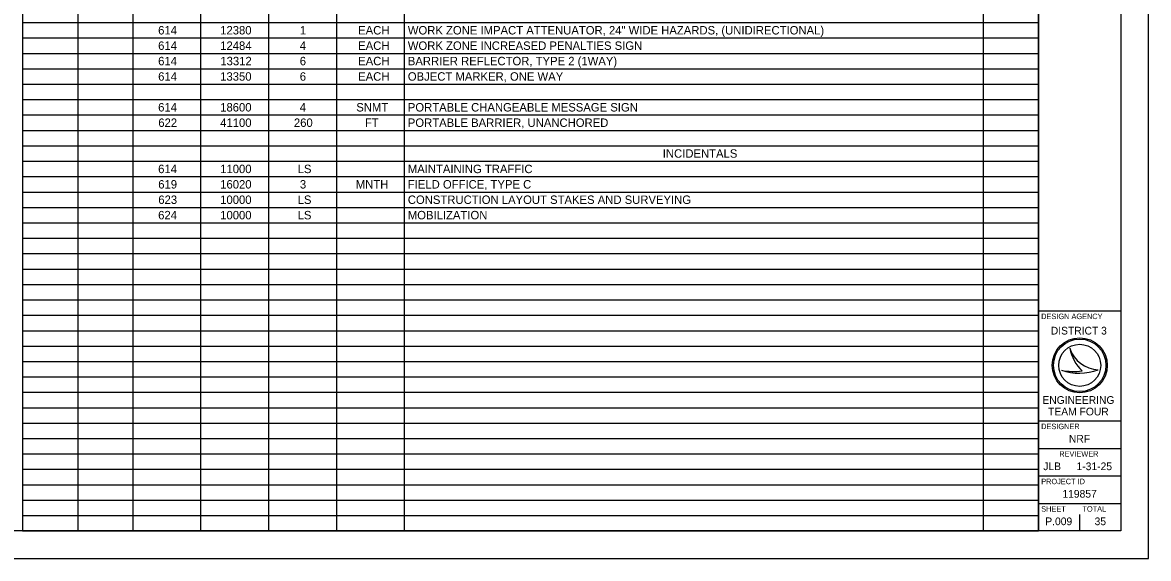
# Model space of a CAD drawing. Extents: x 0 to 34, y 0 to 22.
# Drawn here: x 13.53 to 34, y 0 to 9.74 of the extents above; entities that cross this region are included whole.
import ezdxf

# ---------------------------------------------------------------- set-up
doc = ezdxf.new("R2010")
doc.units = 0
for name, color, linetype in [('Default', 7, 'Continuous'), ('SH_Border', 7, 'Continuous'), ('SH_Cut_Line', 7, 'Continuous'), ('SH_Data', 7, 'Continuous')]:
    doc.layers.add(name, color=color, linetype=linetype)

msp = doc.modelspace()

# ---------------------------------------------------------------- linework, layer by layer
at = {"layer": 'Default'}
for p, q in [((13.53, 10.02), (13.53, 9.74)), ((14.533, 10.02), (14.533, 9.74)), ((15.535, 10.02), (15.535, 9.74)), ((16.769, 10.02), (16.769, 9.74)), ((18.003, 10.02), (18.003, 9.74)), ((19.237, 10.02), (19.237, 9.74)), ((20.471, 10.02), (20.471, 9.74)), ((30.997, 10.02), (30.997, 9.74)), ((32, 10.02), (32, 9.74)), ((13.53, 9.74), (15.535, 9.74)), ((13.53, 9.74), (13.53, 8.9)), ((14.533, 9.74), (14.533, 8.9)), ((15.535, 9.74), (32, 9.74)), ((15.535, 9.74), (15.535, 8.9)), ((16.769, 9.74), (16.769, 8.9)), ((18.003, 9.74), (18.003, 8.9)), ((19.237, 9.74), (19.237, 8.9)), ((20.471, 9.74), (20.471, 8.9)), ((30.997, 9.74), (30.997, 8.9)), ((32, 9.74), (32, 8.9)), ((13.53, 9.46), (15.535, 9.46)), ((15.535, 9.46), (32, 9.46)), ((13.53, 9.18), (15.535, 9.18)), ((15.535, 9.18), (32, 9.18)), ((13.53, 8.9), (15.535, 8.9)), ((13.53, 8.9), (13.53, 8.34)), ((14.533, 8.9), (14.533, 8.34)), ((15.535, 8.9), (32, 8.9)), ((15.535, 8.9), (15.535, 8.34)), ((16.769, 8.9), (16.769, 8.34)), ((18.003, 8.9), (18.003, 8.34)), ((19.237, 8.9), (19.237, 8.34)), ((20.471, 8.9), (20.471, 8.34)), ((30.997, 8.9), (30.997, 8.34)), ((32, 8.9), (32, 8.34)), ((13.53, 8.62), (15.535, 8.62)), ((15.535, 8.62), (32, 8.62)), ((13.53, 8.34), (15.535, 8.34)), ((13.53, 8.34), (13.53, 7.5)), ((14.533, 8.34), (14.533, 7.5)), ((15.535, 8.34), (32, 8.34)), ((15.535, 8.34), (15.535, 7.5)), ((16.769, 8.34), (16.769, 7.5)), ((18.003, 8.34), (18.003, 7.5)), ((19.237, 8.34), (19.237, 7.5)), ((20.471, 8.34), (20.471, 7.5)), ((30.997, 8.34), (30.997, 7.5)), ((32, 8.34), (32, 7.5)), ((13.53, 8.06), (15.535, 8.06)), ((15.535, 8.06), (32, 8.06)), ((13.53, 7.78), (15.535, 7.78)), ((15.535, 7.78), (32, 7.78)), ((13.53, 7.5), (15.535, 7.5)), ((13.53, 7.5), (13.53, 6.94)), ((14.533, 7.5), (14.533, 6.94)), ((15.535, 7.5), (32, 7.5)), ((15.535, 7.5), (15.535, 6.94)), ((16.769, 7.5), (16.769, 6.94)), ((18.003, 7.5), (18.003, 6.94)), ((19.237, 7.5), (19.237, 6.94)), ((20.471, 7.5), (20.471, 6.94)), ((30.997, 7.5), (30.997, 6.94)), ((32, 7.5), (32, 6.94)), ((13.53, 7.22), (15.535, 7.22)), ((15.535, 7.22), (32, 7.22)), ((13.53, 6.94), (15.535, 6.94)), ((13.53, 6.94), (13.53, 6.1)), ((14.533, 6.94), (14.533, 6.1)), ((15.535, 6.94), (32, 6.94)), ((15.535, 6.94), (15.535, 6.1)), ((16.769, 6.94), (16.769, 6.1)), ((18.003, 6.94), (18.003, 6.1)), ((19.237, 6.94), (19.237, 6.1)), ((20.471, 6.94), (20.471, 6.1)), ((30.997, 6.94), (30.997, 6.1)), ((32, 6.94), (32, 6.1)), ((13.53, 6.66), (15.535, 6.66)), ((15.535, 6.66), (32, 6.66)), ((13.53, 6.38), (15.535, 6.38)), ((15.535, 6.38), (32, 6.38)), ((13.53, 6.1), (15.535, 6.1)), ((13.53, 6.1), (13.53, 4.98)), ((14.533, 6.1), (14.533, 4.98)), ((15.535, 6.1), (32, 6.1)), ((15.535, 6.1), (15.535, 4.98)), ((16.769, 6.1), (16.769, 4.98)), ((18.003, 6.1), (18.003, 4.98)), ((19.237, 6.1), (19.237, 4.98)), ((20.471, 6.1), (20.471, 4.98)), ((30.997, 6.1), (30.997, 4.98)), ((32, 6.1), (32, 4.98)), ((13.53, 5.82), (15.535, 5.82)), ((15.535, 5.82), (32, 5.82)), ((13.53, 5.54), (15.535, 5.54)), ((15.535, 5.54), (32, 5.54)), ((13.53, 5.26), (15.535, 5.26)), ((15.535, 5.26), (32, 5.26)), ((13.53, 4.98), (15.535, 4.98)), ((13.53, 4.98), (13.53, 4.7)), ((14.533, 4.98), (14.533, 4.7)), ((15.535, 4.98), (32, 4.98)), ((15.535, 4.98), (15.535, 4.7)), ((16.769, 4.98), (16.769, 4.7)), ((18.003, 4.98), (18.003, 4.7)), ((19.237, 4.98), (19.237, 4.7)), ((20.471, 4.98), (20.471, 4.7)), ((30.997, 4.98), (30.997, 4.7)), ((32, 4.98), (32, 4.7)), ((13.53, 4.7), (15.535, 4.7)), ((13.53, 4.7), (13.53, 3.58)), ((14.533, 4.7), (14.533, 3.58)), ((15.535, 4.7), (32, 4.7)), ((15.535, 4.7), (15.535, 3.58)), ((16.769, 4.7), (16.769, 3.58)), ((18.003, 4.7), (18.003, 3.58)), ((19.237, 4.7), (19.237, 3.58)), ((20.471, 4.7), (20.471, 3.58)), ((30.997, 4.7), (30.997, 3.58)), ((32, 4.7), (32, 3.58)), ((13.53, 4.42), (15.535, 4.42)), ((15.535, 4.42), (32, 4.42)), ((13.53, 4.14), (15.535, 4.14)), ((15.535, 4.14), (32, 4.14)), ((13.53, 3.86), (15.535, 3.86)), ((15.535, 3.86), (32, 3.86)), ((13.53, 3.58), (15.535, 3.58)), ((13.53, 3.58), (13.53, 3.3)), ((14.533, 3.58), (14.533, 3.3)), ((15.535, 3.58), (32, 3.58)), ((15.535, 3.58), (15.535, 3.3)), ((16.769, 3.58), (16.769, 3.3)), ((18.003, 3.58), (18.003, 3.3)), ((19.237, 3.58), (19.237, 3.3)), ((20.471, 3.58), (20.471, 3.3)), ((30.997, 3.58), (30.997, 3.3)), ((32, 3.58), (32, 3.3)), ((13.53, 3.3), (15.535, 3.3)), ((13.53, 3.3), (13.53, 2.18)), ((14.533, 3.3), (14.533, 2.18)), ((15.535, 3.3), (32, 3.3)), ((15.535, 3.3), (15.535, 2.18)), ((16.769, 3.3), (16.769, 2.18)), ((18.003, 3.3), (18.003, 2.18)), ((19.237, 3.3), (19.237, 2.18)), ((20.471, 3.3), (20.471, 2.18)), ((30.997, 3.3), (30.997, 2.18)), ((32, 3.3), (32, 2.18)), ((13.53, 3.02), (15.535, 3.02)), ((15.535, 3.02), (32, 3.02)), ((13.53, 2.74), (15.535, 2.74)), ((15.535, 2.74), (32, 2.74)), ((13.53, 2.46), (15.535, 2.46)), ((15.535, 2.46), (32, 2.46)), ((13.53, 2.18), (15.535, 2.18)), ((13.53, 2.18), (13.53, 1.9)), ((14.533, 2.18), (14.533, 1.9)), ((15.535, 2.18), (32, 2.18)), ((15.535, 2.18), (15.535, 1.9)), ((16.769, 2.18), (16.769, 1.9)), ((18.003, 2.18), (18.003, 1.9)), ((19.237, 2.18), (19.237, 1.9)), ((20.471, 2.18), (20.471, 1.9)), ((30.997, 2.18), (30.997, 1.9)), ((32, 2.18), (32, 1.9)), ((13.53, 1.9), (15.535, 1.9)), ((13.53, 1.9), (13.53, 0.78)), ((14.533, 1.9), (14.533, 0.78)), ((15.535, 1.9), (32, 1.9)), ((15.535, 1.9), (15.535, 0.78)), ((16.769, 1.9), (16.769, 0.78)), ((18.003, 1.9), (18.003, 0.78)), ((19.237, 1.9), (19.237, 0.78)), ((20.471, 1.9), (20.471, 0.78)), ((30.997, 1.9), (30.997, 0.78)), ((32, 1.9), (32, 0.78)), ((13.53, 1.62), (15.535, 1.62)), ((15.535, 1.62), (32, 1.62)), ((13.53, 1.34), (15.535, 1.34)), ((15.535, 1.34), (32, 1.34)), ((13.53, 1.06), (15.535, 1.06)), ((15.535, 1.06), (32, 1.06)), ((13.53, 0.78), (15.535, 0.78)), ((13.53, 0.78), (13.53, 0.5)), ((14.533, 0.78), (14.533, 0.5)), ((15.535, 0.78), (32, 0.78)), ((15.535, 0.78), (15.535, 0.5)), ((16.769, 0.78), (16.769, 0.5)), ((18.003, 0.78), (18.003, 0.5)), ((19.237, 0.78), (19.237, 0.5)), ((20.471, 0.78), (20.471, 0.5)), ((30.997, 0.78), (30.997, 0.5)), ((32, 0.78), (32, 0.5)), ((13.53, 0.5), (15.535, 0.5)), ((15.535, 0.5), (32, 0.5))]:
    msp.add_line(p, q, dxfattribs=at)
at = {"layer": 'SH_Border'}
for p, q in [((32, 0.5), (32, 21.5)), ((32, 4.5), (33.5, 4.5)), ((32, 2.5), (33.5, 2.5)), ((32, 2), (33.5, 2)), ((32, 1.5), (33.5, 1.5)), ((32, 1), (33.5, 1))]:
    msp.add_line(p, q, dxfattribs=at)
msp.add_lwpolyline([(1.5, 21.5), (33.5, 21.5), (33.5, 0.5), (1.5, 0.5)], close=True, dxfattribs=at)
at = {"layer": 'SH_Cut_Line'}
msp.add_lwpolyline([(0, 0), (34, 0), (34, 22), (0, 22)], close=True, dxfattribs=at)
at = {"layer": 'SH_Data'}
for p, q in [((32.567, 3.82), (32.567, 3.82)), ((32.75, 3.5), (32.75, 3.5)), ((32.417, 3.42), (32.417, 3.42)), ((33.087, 3.429), (33.087, 3.429)), ((32.375, 0.675), (32.375, 0.675)), ((32.75, 0.5), (32.75, 0.8))]:
    msp.add_line(p, q, dxfattribs=at)
for radius in [0.5, 0.477, 0.477, 0.382]:
    msp.add_circle((32.75, 3.51), radius, dxfattribs=at)
for centre, radius, start, end in [((33.116, 4.008), 0.58, 198.9257, 198.9319), ((33.347, 3.981), 0.796, 191.6379, 191.6421), ((33.116, 4.008), 0.58, 198.9319, 267.1657), ((33.347, 3.981), 0.796, 191.6421, 226.0947), ((32.739, 4.38), 1.013, 251.4576, 290.0832), ((32.648, 4.665), 1.266, 259.4964, 259.4995), ((32.739, 4.38), 1.013, 251.4527, 251.4576), ((32.648, 4.665), 1.266, 259.4995, 276.6672)]:
    msp.add_arc(centre, radius, start, end, dxfattribs=at)

# ---------------------------------------------------------------- texts
at = {"layer": 'Default'}
for s, height, p in [('614', 0.1533, (15.996, 9.523)), ('12380', 0.1533, (17.124, 9.523)), ('1', 0.153, (18.573, 9.523)), ('EACH', 0.1533, (19.632, 9.523)), ('WORK ZONE IMPACT ATTENUATOR, 24" WIDE HAZARDS, (UNIDIRECTIONAL)', 0.15333, (20.535, 9.523)), ('614', 0.1533, (15.996, 9.243)), ('12484', 0.1533, (17.124, 9.243)), ('4', 0.153, (18.57, 9.243)), ('EACH', 0.1533, (19.632, 9.243)), ('WORK ZONE INCREASED PENALTIES SIGN', 0.15333, (20.535, 9.243)), ('614', 0.1533, (15.996, 8.963)), ('13312', 0.1533, (17.127, 8.963)), ('6', 0.153, (18.571, 8.963)), ('EACH', 0.1533, (19.632, 8.963)), ('BARRIER REFLECTOR, TYPE 2 (1WAY)', 0.15333, (20.535, 8.963)), ('614', 0.1533, (15.996, 8.683)), ('13350', 0.1533, (17.124, 8.683)), ('6', 0.153, (18.571, 8.683)), ('EACH', 0.1533, (19.632, 8.683)), ('OBJECT MARKER, ONE WAY', 0.15333, (20.535, 8.683)), ('614', 0.1533, (15.996, 8.123)), ('18600', 0.1533, (17.124, 8.123)), ('4', 0.153, (18.57, 8.123)), ('SNMT', 0.1533, (19.598, 8.123)), ('PORTABLE CHANGEABLE MESSAGE SIGN', 0.15333, (20.535, 8.123)), ('622', 0.1533, (15.999, 7.843)), ('41100', 0.1533, (17.124, 7.843)), ('260', 0.1533, (18.464, 7.843)), ('FT', 0.1533, (19.756, 7.843)), ('PORTABLE BARRIER, UNANCHORED', 0.15333, (20.535, 7.843)), ('INCIDENTALS', 0.15333, (25.17, 7.283)), ('614', 0.1533, (15.996, 7.003)), ('11000', 0.1533, (17.124, 7.003)), ('LS', 0.1533, (18.532, 7.003)), ('MAINTAINING TRAFFIC', 0.15333, (20.535, 7.003)), ('619', 0.1533, (15.998, 6.723)), ('16020', 0.1533, (17.124, 6.723)), ('3', 0.153, (18.573, 6.723)), ('MNTH', 0.1533, (19.589, 6.723)), ('FIELD OFFICE, TYPE C', 0.15333, (20.535, 6.723)), ('623', 0.1533, (15.999, 6.443)), ('10000', 0.1533, (17.124, 6.443)), ('LS', 0.1533, (18.532, 6.443)), ('CONSTRUCTION LAYOUT STAKES AND SURVEYING', 0.15333, (20.535, 6.443)), ('624', 0.1533, (15.996, 6.163)), ('10000', 0.1533, (17.124, 6.163)), ('LS', 0.1533, (18.532, 6.163)), ('MOBILIZATION', 0.15333, (20.535, 6.163))]:
    msp.add_text(s, height=height, dxfattribs=at).set_placement(p)
at = {"layer": 'SH_Data'}
for s, height, p in [('DESIGN AGENCY', 0.1, (32.05, 4.35)), ('DISTRICT 3', 0.14, (32.224, 4.07)), ('ENGINEERING', 0.14, (32.071, 2.81)), ('TEAM FOUR', 0.14, (32.175, 2.6)), ('DESIGNER', 0.1, (32.05, 2.35)), ('NRF', 0.14, (32.553, 2.105)), ('REVIEWER', 0.1, (32.378, 1.85)), ('JLB', 0.14, (32.087, 1.605)), ('1-31-25', 0.14, (32.692, 1.605)), ('PROJECT ID', 0.1, (32.05, 1.35)), ('119857', 0.14, (32.435, 1.105)), ('SHEET', 0.1, (32.05, 0.85)), ('TOTAL', 0.1, (32.8, 0.85)), ('P.009', 0.14, (32.124, 0.605)), ('35', 0.14, (33.02, 0.605))]:
    msp.add_text(s, height=height, dxfattribs=at).set_placement(p)

doc.saveas('drawing.dxf')
